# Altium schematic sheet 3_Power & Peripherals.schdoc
size 309 x 223 mm; Symbol: Artery_A4; Device: Artery_A4; Company: Artery Technology; Drawed: SD; Version: 1.2; Page Size: A4; @Project Name: AT_START_F421_V1.2; @Page Count: 4; @Update Date: 2023-09-05; @Schematic Name: AT_START_F421; @Page No: 3; @Page Name: Power &amp; Peripherals
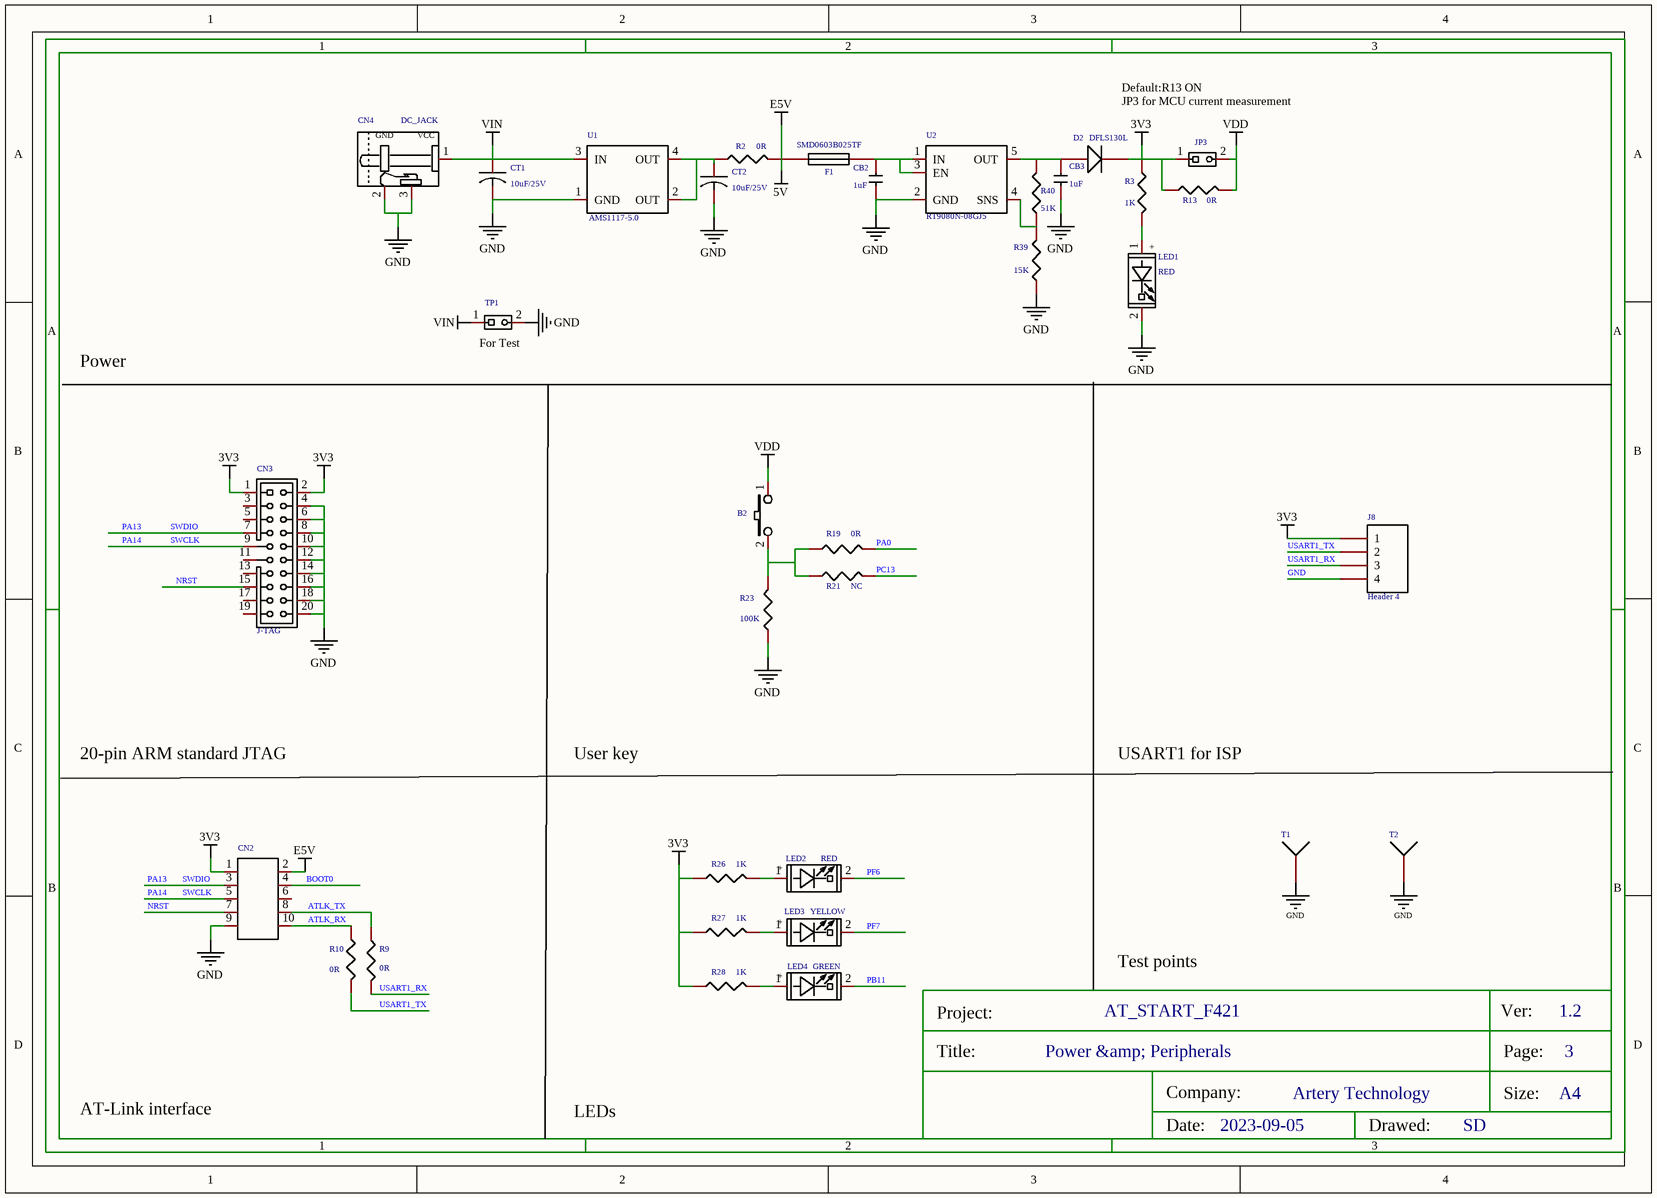
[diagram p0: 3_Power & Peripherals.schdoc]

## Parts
B2  PB,Blue,SMD_2P  [KEY_SOP_6*6]  (value not drawn)
CB2  1uF  [C0603]
CB3  1uF  [C0603]
CN2  CON10  [HDR2X5]  (value not drawn)
CN3  J-TAG  [JTAG_20]
CN4  DC_JACK  [DC10B]
CT1  10uF/25V  [C3528]
CT2  10uF/25V  [C3528]
D2  DFLS130L  [SOD-123]
F1  SMD0603B025TF  [r0603]
J8  Header 4  [HDR1X4]
JP3  1X2P_2.54M  [HDR1X2]  (value not drawn)
LED1  RED  [LED0603]
LED2  RED  [LED0603]
LED3  YELLOW  [LED0603]
LED4  GREEN  [LED0603]
R2  0R  [SB-PAD]
R3  1K  [r0603]
R9  0R  [SB-PAD]
R10  0R  [SB-PAD]
R13  0R  [SB-PAD]
R19  0R  [SB-PAD]
R21  NC  [SB-PAD]
R23  100K  [r0603]
R26  1K  [r0603]
R27  1K  [r0603]
R28  1K  [r0603]
R39  15K  [r0603]
R40  51K  [r0603]
T1  Test point  [TestPoint]  (value not drawn)
T2  Test point  [TestPoint]  (value not drawn)
TP1  1X2P_2.54M  [HDR1X2]  (value not drawn)
U1  AMS1117-5.0  [SOT223]
U2  RT9080N-08GJ5  [SOT-23-5]

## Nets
3V3: CN2.1 CN3.1 CN3.2 D2.2(K) J8.1 JP3.1 R3.1 R13.1 R26.1 R27.1 R28.1
5V: CN2.2 F1.1 R2.2  [also labelled E5V]
GND: CB2.2 CB3.2 CN2.9 CN3.4 CN3.6 CN3.8 CN3.10 CN3.12 CN3.14 CN3.16 CN3.18 CN3.20 CN4.2 CN4.3 CT1.2 CT2.2 J8.4 LED1.2(CATHODE) R23.1 R39.1 T1.1 T2.1 TP1.2 U1.1(GND) U2.2(GND)
VDD: B2.1 JP3.2 R13.2
VIN: CN4.1 CT1.1 TP1.1 U1.3(IN)
ATLK_RX: CN2.10 R10.1
ATLK_TX: CN2.8 R9.1
BOOT0: CN2.4
NRST: CN2.7 CN3.15
PA0: R19.2
PA13: CN2.3 CN3.7  [also labelled SWDIO]
PA14: CN2.5 CN3.9  [also labelled SWCLK]
PB11: LED4.2(CATHODE)
PC13: R21.2
PF6: LED2.2(CATHODE)
PF7: LED3.2(CATHODE)
USART1_RX: J8.3 R9.2
USART1_TX: J8.2 R10.2
NetB2_2: B2.2 R19.1 R21.1 R23.2
NetCB2_1: CB2.1 F1.2 U2.1(IN) U2.3(EN)
NetCB3_1: CB3.1 D2.1(A) R40.2 U2.5(OUT)
NetCT2_1: CT2.1 R2.1 U1.2(OUT) U1.4(OUT)
NetLED1_1: LED1.1(ANODE) R3.2
NetLED2_1: LED2.1(ANODE) R26.2
NetLED3_1: LED3.1(ANODE) R27.2
NetLED4_1: LED4.1(ANODE) R28.2
NetR39_2: R39.2 R40.1 U2.4(SNS)

Not connected (* = marked no-connect by the designer): CN2 6; CN3 3 5 11 13 17 19

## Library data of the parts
B2 = PB,Blue,SMD_2P: 贴片按键6*6*5 蓝色; Symbol: Push_Bottom,Blue,SMD_2P; Add into BOM: yes
CB2 CB3 = 1uF: 贴片陶瓷电容 1uF,25V,X5R,10%,0603; Symbol: 0.1uF,50V,20%,SMD0603; Add into BOM: yes
CN2 = CON10: 简易牛角DC3-10P 双排直插针 2.54mm 2*5P双排 黑色; Symbol: CON10A_0; Add into BOM: yes
CN3 = J-TAG: J-TAG插座，2*10P 2.54mm（黑色）; Symbol: 10x2P,Male,Housing,DIP_2.54; Add into BOM: yes
CN4 = DC_JACK: DC-005直流电源插座5.0*2.1mm（黑色）; Symbol: DC12V_Power_JACK,2.0,DIP_3P; Add into BOM: yes
CT1 CT2 = 10uF/25V: &apos;贴片钽电容 10uF,25V,10%,CASE-B 3528; Symbol: 10uF,16V,20%,B_Case_Dup1; Add into BOM: yes
D2 = DFLS130L: DIODES DFLS130L-7; Symbol: Diode; Add into BOM: yes
F1 = SMD0603B025TF: 可恢复保险丝 SMD0603B025TF; Symbol: Fuse 1; Add into BOM: yes
J8 = Header 4: 单排90度插针1*4P 2.54mm（黑色）; Add into BOM: yes
JP3 = 1X2P_2.54M: Symbol: 1X2P,Male,DIP_2.54; Origin Footprint 2: SIP_2P; Add into BOM: yes
LED1 LED2 = RED: 贴片LED 红色  0603; Symbol: RED,SMD0603; Add into BOM: yes
LED3 = YELLOW: 贴片LED 黄色 0603; Symbol: YELLOW,SMD0603; Add into BOM: yes
LED4 = GREEN: 贴片LED 绿色 0603; Symbol: GREEN,SMD0603; Add into BOM: yes
R2 R9 R10 R13 R19 = 0R: 贴片电阻0R,1/10W,5%,0603; Symbol: 470,1/10W,1%,SMD0603; Add into BOM: yes
R3 R26-R28 = 1K: 贴片电阻1K,1/10W,5%,0603; Symbol: 470,1/10W,1%,SMD0603; Add into BOM: yes
R21 = NC: 贴片电阻0R,1/10W,5%,0603; Symbol: 470,1/10W,1%,SMD0603; Add into BOM: yes
R23 = 100K: 贴片电阻100K,1/10W,5%,0603; Symbol: 10K,1/10W,1%,SMD0603; Add into BOM: yes
R39 = 15K: 贴片电阻15K,1/10W,1%,0603; Symbol: 470,1/10W,1%,SMD0603; Add into BOM: yes
R40 = 51K: 贴片电阻51K,1/10W,1%,0603; Symbol: 470,1/10W,1%,SMD0603; Add into BOM: yes
T1 T2 = Test point: Keystone 美标塑料PCB板测试针环 黑色中号（TP-5006）; Symbol: Socket; Add into BOM: yes
TP1 = 1X2P_2.54M: test point 2x2.54mm; Symbol: 1X2P,Male,DIP_2.54; Origin Footprint 2: SIP_2P; Add into BOM: yes; Origin Footprint 1: HDR1X2 - SOP
U1 = AMS1117-5.0: AMS1117-5.0 SOT223; Symbol: AMS1117-3.3; Add into BOM: yes
U2 = RT9080N-08GJ5: Add into BOM: yes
